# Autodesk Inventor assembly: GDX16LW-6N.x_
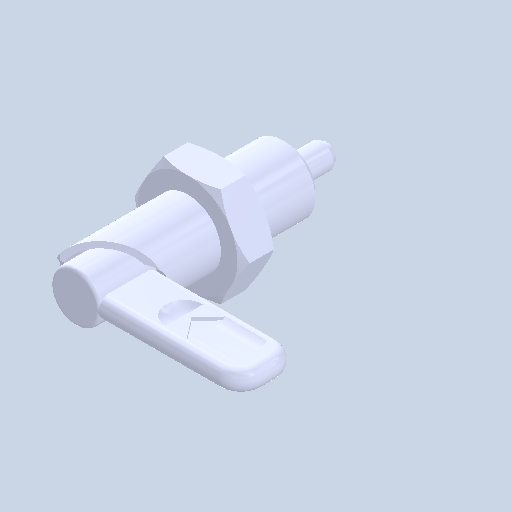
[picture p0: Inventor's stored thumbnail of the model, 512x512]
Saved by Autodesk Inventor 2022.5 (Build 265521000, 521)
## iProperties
Created: 2024-06
Part Number: GDX16LW-6N.x_
Document SubType Name: Assembly
Designer: ImaoCorp
Author: ImaoCorp
Sending System: SOLIDWORKS 2022-2022290
MC: AMD64
MC_MODEL: Intel64 Family 6 Model 60 Stepping 3, GenuineIntel
OS: Windows_NT
FRU: Parasolid Version 33.1, build 260,  4-25-2022
FORMAT: text
GUISE: transmit
KEY: FILEGDX16LW-6N.x_t
DATE: Wed Jun 12 09:32:32 2024
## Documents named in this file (4)
- Y:\5.更新分\2024年対応\xxxx_GDX\データ_imao品番\gdx16lw-6n\GDX16LW-6N.x_.iam
- Y:\5.更新分\2024年対応\xxxx_GDX\データ_imao品番\gdx16lw-6n\GDX16LW-6N_01.ipt
- Y:\5.更新分\2024年対応\xxxx_GDX\データ_imao品番\gdx16lw-6n\GDX16LW-6N_02.ipt
- Y:\5.更新分\2024年対応\xxxx_GDX\データ_imao品番\gdx16lw-6n\GDX16LW-6N_03.ipt
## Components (3 placed, 3 different names)
1. GDX16LW-6N_01
2. GDX16LW-6N_02
3. GDX16LW-6N_03
